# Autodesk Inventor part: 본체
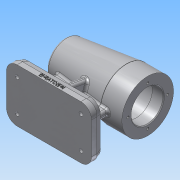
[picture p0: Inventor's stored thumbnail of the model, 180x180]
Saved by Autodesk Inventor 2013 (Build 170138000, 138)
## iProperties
Created: 2017-01
Part Number: 본체
Material: 알루미늄 6061
Document SubType Name: Modeling
Designer: Administrator
Density: 2.71 g/cm^3
Mass: 794.435 g
Surface Area: 664.895 cm^2
Volume: 293.149 cm^3
Author: Administrator
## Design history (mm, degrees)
sketch "스케치1"
  geometry: L1 (28, 34)-(-52.27, 24.144); L2 (28, 34)-(56, 34); L3 (56, 34)-(56, 0); L4 (56, 0)-(-56, 0); A1 r 80 centre (24, 0) between (-52.27, 24.144) and (-56, 0); 2 further points
  constraints: 8 end point, 2 point on circle, 2 point on line, 1 centre point, 1 coincident, 1 horizontal, 1 midpoint, 1 parallel, 1 perpendicular
  dimensions: "d0" = 7 deg angle of L2 L1; "d1" = 28 distance of L1.start L2.end; "d3" = 112 distance from line of A1.end L3; "d4" = 80 radius of A1; "d5" = 68 diameter of L2 L4; "d6" = 56 distance of A1.end point (0, 0)
revolve "회전1" sketch "스케치1" stored, may be unused: angle "d7" = 90 deg
node "작업 평면1"
sketch "스케치2"
  geometry: L1 (56, -35)-(-56, -35); L2 (-56, -35)-(-56, 35); L3 (-56, 35)-(56, 35); L4 (56, 35)-(56, -35); 1 further point
  constraints: 8 end point, 2 parallel, 1 horizontal, 1 perpendicular
  dimensions: "d9" = 56 distance from line of L2 point (0, 0); "d10" = 112 distance between parallel lines of L4 L2; "d11" = 70 distance of L1.end L2.end; "d12" = 35 distance from line of L1 point (0, 0)
extrude "돌출1" join sketch "스케치2" distance "d13" = 7; taper "d14" = 0 deg
sketch "스케치3"
  geometry: L1 (-56, -67)-(56, -67) reference; L2 (-56, -67)-(-54.124, -60); L3 (-54.124, -60)-(54.124, -60); L4 (54.124, -60)-(56, -67); L5 (-56, -74)-(-56, -67) reference; L6 (56, -74)-(56, -67) reference; 1 further point
  constraints: 6 end point, 1 parallel
  dimensions: "d15" = 15 deg angle of L5 L2; "d16" = 15 deg angle of L6 L4; "d17" = 7 distance between parallel lines of L3 L1
extrude "돌출2" join sketch "스케치3" stored distance "d18" = 70; taper "d19" = 0 deg
sketch "스케치4"
  geometry: L1 (70, 0)-(70, 7) reference; L2 (0, 7)-(70, 7) reference; L3 (0, 0)-(0, 7) reference; L4 (0, 7)-(1.876, 14); L5 (1.876, 14)-(68.124, 14); L6 (68.124, 14)-(70, 7); L7 (0, 14)-(70, 14) reference; L8 (70, 7)-(0, 7); L9 (1.876, 14)-(0, 14); L10 (0, 14)-(0, 7); L11 (70, 7)-(70, 14); L12 (70, 14)-(68.124, 14); 1 further point
  constraints: 16 end point, 2 equal length, 1 perpendicular
  dimensions: "d20" = 15 deg angle of L1 L6; "d21" = 15 deg angle of L3 L4; "d23" = 7 distance between parallel lines of L2 L5
extrude "돌출3" cut sketch "스케치4" stored distance "d24" = 70; taper "d25" = 0 deg
sketch "스케치5"
  geometry: L1 (50.124, 49.767)-(58.124, 49.767); L2 (58.124, 49.767)-(58.124, 11.361); L3 (58.124, 11.361)-(50.124, 11.361); L4 (50.124, 11.361)-(50.124, 49.767); L5 (16.124, 37.124)-(92.124, 37.124); L6 (92.124, 37.124)-(92.124, 29.124); L7 (92.124, 29.124)-(16.124, 29.124); L8 (16.124, 29.124)-(16.124, 37.124); L9 (-1.876, 68.124)-(-1.876, -1.876) reference; L10 (110.124, -1.876)-(110.124, 68.124) reference; 1 further point
  constraints: 16 end point, 4 parallel, 2 horizontal, 2 perpendicular
  dimensions: "d27" = 4 distance from line of L5 point (54.124, 33.124); "d28" = 8 distance between parallel lines of L7 L5; "d29" = 4 distance from line of L4 point (54.124, 33.124); "d30" = 8 distance between parallel lines of L2 L4; "d31" = 18 distance between parallel lines of L9 L8; "d32" = 18 distance between parallel lines of L10 L6
extrude "돌출4" join sketch "스케치5" stored distance "d33" = 70; taper "d34" = 0 deg
sketch "스케치6"
  geometry: L1 (-26.866, 17.158)-(-60, 23); L2 (-60, -33.124)-(-60, 33.124) reference; L3 (-74, 35)-(-67, 35) reference; 1 further point
  constraints: 2 end point, 1 point on line
  dimensions: "d35" = 100 deg angle of L2 L1; "d36" = 12 distance from line of L1.end L3
feature "리브1" sketch "스케치6" dims "d37" = 1, "d38" = 8, "d39" = 0, "d40" = 0, "d41" = 1, "d42" = 1
sketch "스케치7"
  geometry: L1 (56, -34)-(56, 34) reference; L2 (28, 34)-(56, 34) reference; L3 (-52.27, 24.144)-(28, 34) reference; L4 (41, 0)-(56, 0); L5 (56, 0)-(56, 21); L6 (56, 21)-(41, 21); L7 (41, 21)-(41, 0); L8 (41, 0)-(-13, 0); L9 (-13, 0)-(-13, 24); L10 (-13, 24)-(41, 24); L11 (41, 24)-(41, 0); L12 (-13, 0)-(-25, 0); L13 (-25, 0)-(-25, 21); L14 (-25, 21)-(-13, 21); L15 (-13, 21)-(-13, 0); L16 (-25, 0)-(-43, 0); L17 (-43, 0)-(-43, 17.5); L18 (-43, 17.5)-(-25, 17.5); L19 (-25, 17.5)-(-25, 0); L20 (-43, 0)-(-47, 0); L21 (-47, 0)-(-47, 16); L22 (-47, 16)-(-43, 16); L23 (-43, 16)-(-43, 0); L24 (-47, 0)-(-50, 0); L25 (-50, 0)-(-50, 10.5); L26 (-50, 10.5)-(-47, 10.5); L27 (-47, 10.5)-(-47, 0); A1 r 80 centre (24, 0) between (-52.27, 24.144) and (-52.27, -24.144) reference; 2 further points
  constraints: 48 end point, 12 parallel, 6 horizontal, 6 perpendicular, 3 point on line, 1 midpoint
  dimensions: "d50" = 15 distance between parallel lines of L7 L1; "d51" = 54 distance between parallel lines of L15 L7; "d52" = 42 diameter of L6 L4; "d54" = 48 diameter of L10 L8; "d55" = 12 distance between parallel lines of L19 L15; "d57" = 35 diameter of L18 L16; "d58" = 42 diameter of L14 L12; "d59" = 32 diameter of L22 L20; "d60" = 18 distance between parallel lines of L13 L17; "d61" = 4 distance between parallel lines of L21 L17; "d62" = 3 distance between parallel lines of L25 L21; "d63" = 21 diameter of L26 L24
revolve "회전2" sketch "스케치7" stored, may be unused: angle "d64" = 90 deg
fillet "모깎기1" dims "d65" = 3
sketch "스케치8"
  geometry: C1 r 21 at (0, 0) reference; 1 further point
  constraints: 1 vertical alignment
  dimensions: "d66" = 26 distance of C1.centre point (0, 26)
hole "구멍1" sketch "스케치8" at (0, 26) diameter "d67" = 3.242; stored, may be unused: countersink angle "d71" = 90 deg, drill point angle "d73" = 118 deg; dims "d68" = 8, "d69" = 4, "d70" = 2, "d72" = 11
fillet "모깎기2" dims "d77" = 0.3
fillet "모깎기4" dims "d79" = 14
fillet "모깎기5" dims "d80" = 14
sketch "스케치9" dims "d82" = 5
  geometry: L1 (81.203, 66.249)-(0, 66.249) reference; L2 (-1.399, 68.124)-(82.601, 68.124) reference; L3 (-15.399, 54.124)-(-15.399, 12.124) reference; L4 (40.601, 33.124)-(40.601, 49.124); L5 (77.733, 55.262)-(79.181, 50.477); L6 (79.181, 50.477)-(84.05, 49.339); L7 (86.021, 57.772)-(81.153, 58.91); L8 (87.47, 52.986)-(86.021, 57.772); L9 (84.05, 49.339)-(87.47, 52.986); L10 (81.153, 58.91)-(77.733, 55.262); L11 (1.101, 58.454)-(3.601, 54.124); L12 (3.601, 54.124)-(1.101, 49.794); L13 (1.101, 49.794)-(-3.899, 49.794); L14 (-3.899, 49.794)-(-6.399, 54.124); L15 (-6.399, 54.124)-(-3.899, 58.454); L16 (-3.899, 58.454)-(1.101, 58.454); 8 further points; 1 other entity
  constraints: 26 end point, 3 coincident, 3 symmetric about line, 2 parallel, 1 vertical, 20 other
  dimensions: "d84" = 14 distance from line of L2 point (-1.399, 54.124); "d85" = 14 distance from line of L3 point (-1.399, 54.124)
extrude "돌출5" cut sketch "스케치9" distance "d86" = 4; taper "d87" = 0 deg
sketch "스케치10"
  geometry: L1 (1.101, 49.794)-(-3.899, 49.794) reference; L2 (3.601, 54.124)-(-6.399, 54.124); C1 r 2.5 at (-1.399, 54.124); 1 further point
  constraints: 2 end point, 1 centre point, 1 midpoint, 1 parallel
  dimensions: "d88" = 2.5 radius of C1
extrude "돌출6" cut sketch "스케치10" stored distance "d89" = 4; taper "d90" = 0 deg
fillet "모깎기6" dims "d91" = 3
fillet "모깎기7" dims "d92" = 3
node "작업 평면2"
sketch "스케치11"
  geometry: L1 (42, -74)-(-42, -74) reference; L2 (56, -74)-(56, -67) reference; 2 further points
  constraints: 1 other
  dimensions: "d95" = 4 distance from line of L1 point (0, -70); "d96" = 56 distance from line of L2 point (0, -70)
feature "엠보싱1" sketch "스케치11" dims "d0" = 7 deg, "d1" = 28, "d3" = 112, "d4" = 80, "d5" = 68, "d6" = 56, "d15" = 15 deg, "d16" = 15 deg, "d17" = 7, "d97" = 0.5, "d98" = 0
chamfer "모따기1" distance "d99" = 1; stored, may be unused: second distance "d100" = 2, angle "d101" = 45 deg
fillet "모깎기9" dims "d102" = 1
fillet "모깎기10" dims "d103" = 3
fillet "모깎기11" dims "d104" = 3
fillet "모깎기12" dims "d105" = 3
node "솔리드1"
mirror "대칭1"
pattern_circular "원형 패턴1" dims angle "d75" = 360 deg
mirror "대칭2"
mirror "대칭3"
other parameters: "d8" = -74, "d94" = 70.5
